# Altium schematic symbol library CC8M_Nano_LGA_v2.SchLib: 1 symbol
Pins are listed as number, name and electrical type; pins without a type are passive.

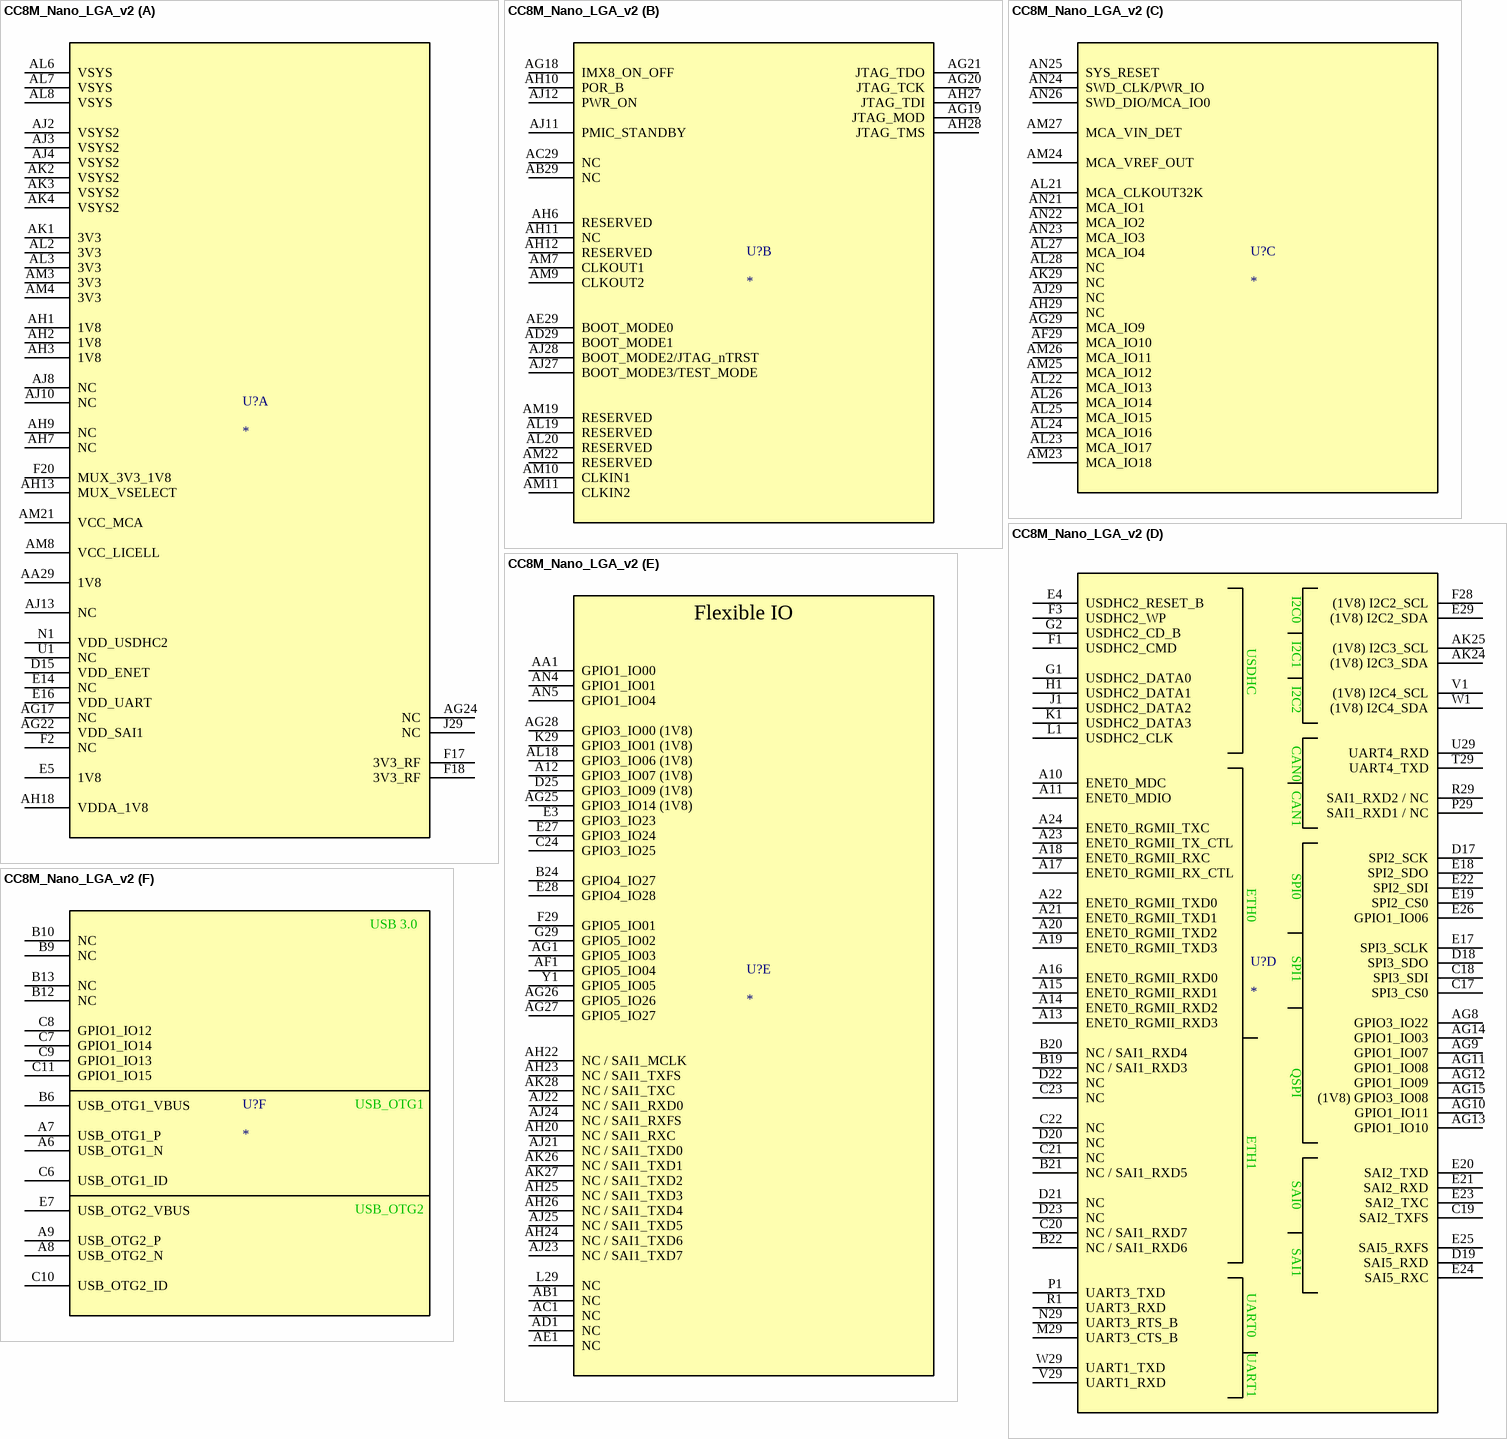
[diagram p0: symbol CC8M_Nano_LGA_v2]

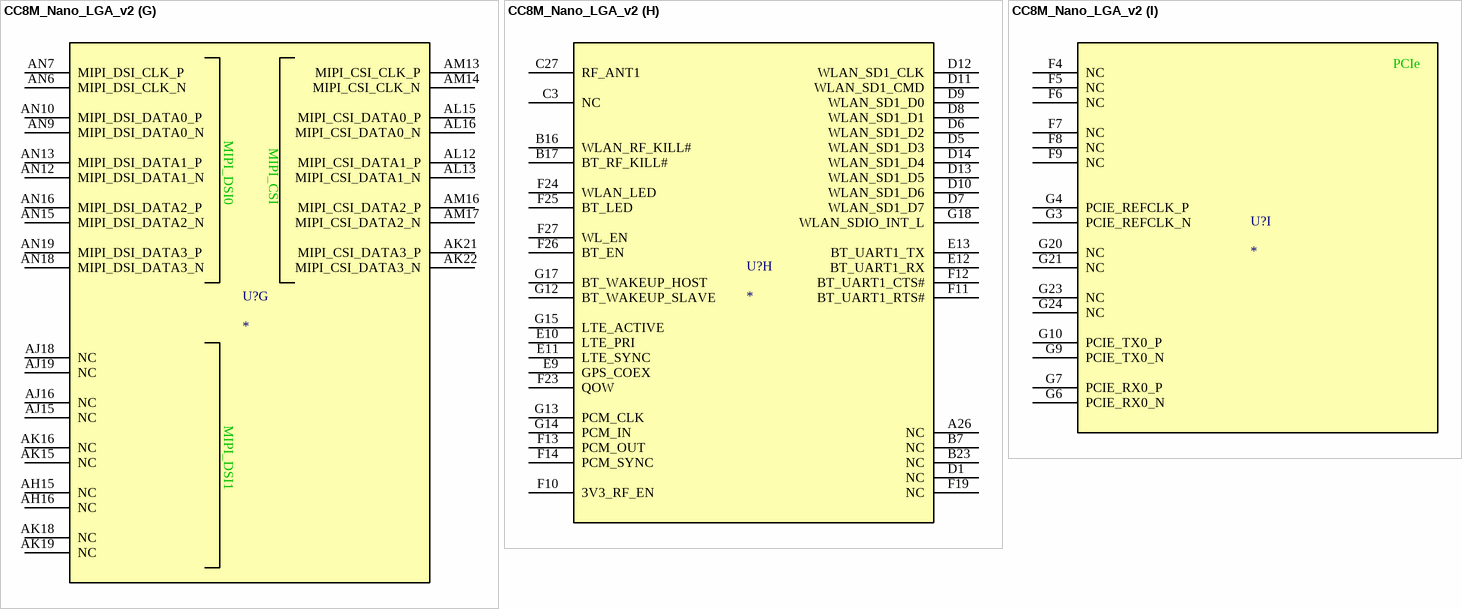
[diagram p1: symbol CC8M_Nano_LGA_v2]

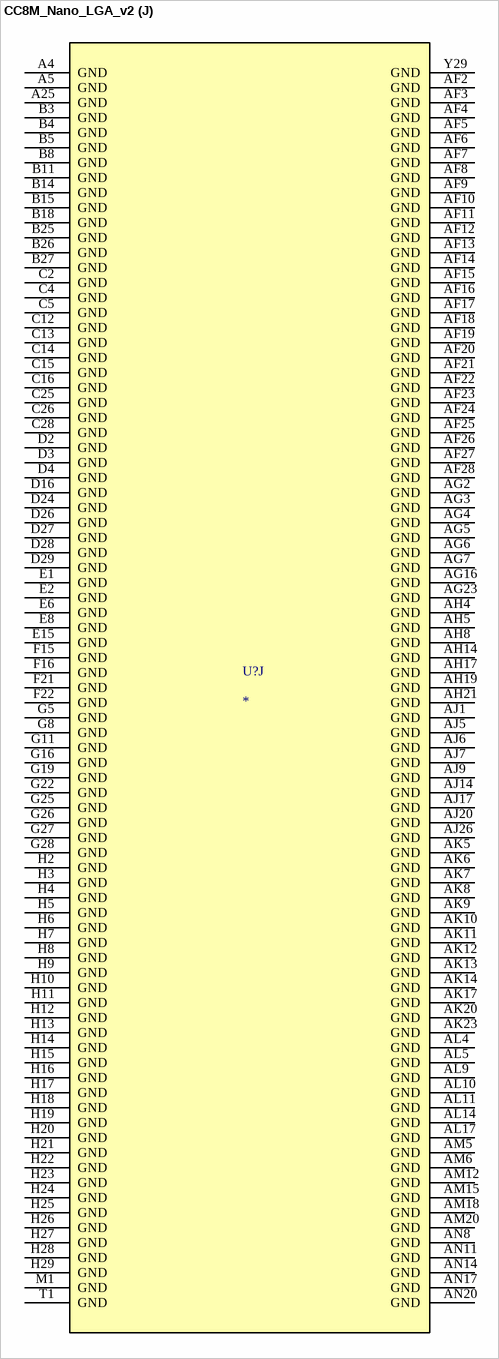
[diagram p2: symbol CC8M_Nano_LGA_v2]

## CC8M_Nano_LGA_v2
designator U?
part A pins: AA29 1V8, AG17 NC, AG22 VDD_SAI1, AG24 NC, AH1 1V8, AH2 1V8, AH3 1V8, AH7 NC, AH9 NC, AH13 MUX_VSELECT, AH18 VDDA_1V8, AJ2 VSYS2, AJ3 VSYS2, AJ4 VSYS2, AJ8 NC, AJ10 NC, AJ13 NC, AK1 3V3, AK2 VSYS2, AK3 VSYS2, AK4 VSYS2, AL2 3V3, AL3 3V3, AL6 VSYS, AL7 VSYS, AL8 VSYS, AM3 3V3, AM4 3V3, AM8 VCC_LICELL, AM21 VCC_MCA, D15 VDD_ENET, E5 1V8, E14 NC, E16 VDD_UART, F2 NC, F17 3V3_RF, F18 3V3_RF, F20 MUX_3V3_1V8, J29 NC, N1 VDD_USDHC2, U1 NC
part B pins: AB29 NC, AC29 NC, AD29 BOOT_MODE1, AE29 BOOT_MODE0, AG18 IMX8_ON_OFF, AG19 JTAG_MOD, AG20 JTAG_TCK, AG21 JTAG_TDO, AH6 RESERVED, AH10 POR_B, AH11 NC, AH12 RESERVED, AH27 JTAG_TDI, AH28 JTAG_TMS, AJ11 PMIC_STANDBY, AJ12 PWR_ON, AJ27 BOOT_MODE3/TEST_MODE, AJ28 BOOT_MODE2/JTAG_nTRST, AL19 RESERVED, AL20 RESERVED, AM7 CLKOUT1, AM9 CLKOUT2, AM10 CLKIN1, AM11 CLKIN2, AM19 RESERVED, AM22 RESERVED
part C pins: AF29 MCA_IO10, AG29 MCA_IO9, AH29 NC, AJ29 NC, AK29 NC, AL21 MCA_CLKOUT32K, AL22 MCA_IO13, AL23 MCA_IO17, AL24 MCA_IO16, AL25 MCA_IO15, AL26 MCA_IO14, AL27 MCA_IO4, AL28 NC, AM23 MCA_IO18, AM24 MCA_VREF_OUT, AM25 MCA_IO12, AM26 MCA_IO11, AM27 MCA_VIN_DET, AN21 MCA_IO1, AN22 MCA_IO2, AN23 MCA_IO3, AN24 SWD_CLK/PWR_IO, AN25 SYS_RESET, AN26 SWD_DIO/MCA_IO0
part D pins: A10 ENET0_MDC, A11 ENET0_MDIO, A13 ENET0_RGMII_RXD3, A14 ENET0_RGMII_RXD2, A15 ENET0_RGMII_RXD1, A16 ENET0_RGMII_RXD0, A17 ENET0_RGMII_RX_CTL, A18 ENET0_RGMII_RXC, A19 ENET0_RGMII_TXD3, A20 ENET0_RGMII_TXD2, A21 ENET0_RGMII_TXD1, A22 ENET0_RGMII_TXD0, A23 ENET0_RGMII_TX_CTL, A24 ENET0_RGMII_TXC, AG8 GPIO3_IO22, AG9 GPIO1_IO07, AG10 GPIO1_IO11, AG11 GPIO1_IO08, AG12 GPIO1_IO09, AG13 GPIO1_IO10, AG14 GPIO1_IO03, AG15 (1V8) GPIO3_IO08, AK24 (1V8) I2C3_SDA, AK25 (1V8) I2C3_SCL, B19 NC / SAI1_RXD3, B20 NC / SAI1_RXD4, B21 NC / SAI1_RXD5, B22 NC / SAI1_RXD6, C17 SPI3_CS0, C18 SPI3_SDI, C19 SAI2_TXFS, C20 NC / SAI1_RXD7, C21 NC, C22 NC, C23 NC, D17 SPI2_SCK, D18 SPI3_SDO, D19 SAI5_RXD, D20 NC, D21 NC, D22 NC, D23 NC, E4 USDHC2_RESET_B, E17 SPI3_SCLK, E18 SPI2_SDO, E19 SPI2_CS0, E20 SAI2_TXD, E21 SAI2_RXD, E22 SPI2_SDI, E23 SAI2_TXC, E24 SAI5_RXC, E25 SAI5_RXFS, E26 GPIO1_IO06, E29 (1V8) I2C2_SDA, F1 USDHC2_CMD, F3 USDHC2_WP, F28 (1V8) I2C2_SCL, G1 USDHC2_DATA0, G2 USDHC2_CD_B, H1 USDHC2_DATA1, J1 USDHC2_DATA2, K1 USDHC2_DATA3, L1 USDHC2_CLK, M29 UART3_CTS_B, N29 UART3_RTS_B, P1 UART3_TXD, P29 SAI1_RXD1 / NC, R1 UART3_RXD, R29 SAI1_RXD2 / NC, T29 UART4_TXD, U29 UART4_RXD, V1 (1V8) I2C4_SCL, V29 UART1_RXD, W1 (1V8) I2C4_SDA, W29 UART1_TXD
part E pins: A12 GPIO3_IO07 (1V8), AA1 GPIO1_IO00, AB1 NC, AC1 NC, AD1 NC, AE1 NC, AF1 GPIO5_IO04, AG1 GPIO5_IO03, AG25 GPIO3_IO14 (1V8), AG26 GPIO5_IO26, AG27 GPIO5_IO27, AG28 GPIO3_IO00 (1V8), AH20 NC / SAI1_RXC, AH22 NC / SAI1_MCLK, AH23 NC / SAI1_TXFS, AH24 NC / SAI1_TXD6, AH25 NC / SAI1_TXD3, AH26 NC / SAI1_TXD4, AJ21 NC / SAI1_TXD0, AJ22 NC / SAI1_RXD0, AJ23 NC / SAI1_TXD7, AJ24 NC / SAI1_RXFS, AJ25 NC / SAI1_TXD5, AK26 NC / SAI1_TXD1, AK27 NC / SAI1_TXD2, AK28 NC / SAI1_TXC, AL18 GPIO3_IO06 (1V8), AN4 GPIO1_IO01, AN5 GPIO1_IO04, B24 GPIO4_IO27, C24 GPIO3_IO25, D25 GPIO3_IO09 (1V8), E3 GPIO3_IO23, E27 GPIO3_IO24, E28 GPIO4_IO28, F29 GPIO5_IO01, G29 GPIO5_IO02, K29 GPIO3_IO01 (1V8), L29 NC, Y1 GPIO5_IO05
part F pins: A6 USB_OTG1_N, A7 USB_OTG1_P, A8 USB_OTG2_N, A9 USB_OTG2_P, B6 USB_OTG1_VBUS, B9 NC, B10 NC, B12 NC, B13 NC, C6 USB_OTG1_ID, C7 GPIO1_IO14, C8 GPIO1_IO12, C9 GPIO1_IO13, C10 USB_OTG2_ID, C11 GPIO1_IO15, E7 USB_OTG2_VBUS
part G pins: AH15 NC, AH16 NC, AJ15 NC, AJ16 NC, AJ18 NC, AJ19 NC, AK15 NC, AK16 NC, AK18 NC, AK19 NC, AK21 MIPI_CSI_DATA3_P, AK22 MIPI_CSI_DATA3_N, AL12 MIPI_CSI_DATA1_P, AL13 MIPI_CSI_DATA1_N, AL15 MIPI_CSI_DATA0_P, AL16 MIPI_CSI_DATA0_N, AM13 MIPI_CSI_CLK_P, AM14 MIPI_CSI_CLK_N, AM16 MIPI_CSI_DATA2_P, AM17 MIPI_CSI_DATA2_N, AN6 MIPI_DSI_CLK_N, AN7 MIPI_DSI_CLK_P, AN9 MIPI_DSI_DATA0_N, AN10 MIPI_DSI_DATA0_P, AN12 MIPI_DSI_DATA1_N, AN13 MIPI_DSI_DATA1_P, AN15 MIPI_DSI_DATA2_N, AN16 MIPI_DSI_DATA2_P, AN18 MIPI_DSI_DATA3_N, AN19 MIPI_DSI_DATA3_P
part H pins: A26 NC, B7 NC, B16 WLAN_RF_KILL#, B17 BT_RF_KILL#, B23 NC, C3 NC, C27 RF_ANT1, D1 NC, D5 WLAN_SD1_D3, D6 WLAN_SD1_D2, D7 WLAN_SD1_D7, D8 WLAN_SD1_D1, D9 WLAN_SD1_D0, D10 WLAN_SD1_D6, D11 WLAN_SD1_CMD, D12 WLAN_SD1_CLK, D13 WLAN_SD1_D5, D14 WLAN_SD1_D4, E9 GPS_COEX, E10 LTE_PRI, E11 LTE_SYNC, E12 BT_UART1_RX, E13 BT_UART1_TX, F10 3V3_RF_EN, F11 BT_UART1_RTS#, F12 BT_UART1_CTS#, F13 PCM_OUT, F14 PCM_SYNC, F19 NC, F23 QOW, F24 WLAN_LED, F25 BT_LED, F26 BT_EN, F27 WL_EN, G12 BT_WAKEUP_SLAVE, G13 PCM_CLK, G14 PCM_IN, G15 LTE_ACTIVE, G17 BT_WAKEUP_HOST, G18 WLAN_SDIO_INT_L
part I pins: F4 NC, F5 NC, F6 NC, F7 NC, F8 NC, F9 NC, G3 PCIE_REFCLK_N, G4 PCIE_REFCLK_P, G6 PCIE_RX0_N, G7 PCIE_RX0_P, G9 PCIE_TX0_N, G10 PCIE_TX0_P, G20 NC, G21 NC, G23 NC, G24 NC
part J pins:  A25 GND, A4 GND, A5 GND, AF2 GND, AF3 GND, AF4 GND, AF5 GND, AF6 GND, AF7 GND, AF8 GND, AF9 GND, AF10 GND, AF11 GND, AF12 GND, AF13 GND, AF14 GND, AF15 GND, AF16 GND, AF17 GND, AF18 GND, AF19 GND, AF20 GND, AF21 GND, AF22 GND, AF23 GND, AF24 GND, AF25 GND, AF26 GND, AF27 GND, AF28 GND, AG2 GND, AG3 GND, AG4 GND, AG5 GND, AG6 GND, AG7 GND, AG16 GND, AG23 GND, AH4 GND, AH5 GND, AH8 GND, AH14 GND, AH17 GND, AH19 GND, AH21 GND, AJ1 GND, AJ5 GND, AJ6 GND, AJ7 GND, AJ9 GND, AJ14 GND, AJ17 GND, AJ20 GND, AJ26 GND, AK5 GND, AK6 GND, AK7 GND, AK8 GND, AK9 GND, AK10 GND, AK11 GND, AK12 GND, AK13 GND, AK14 GND, AK17 GND, AK20 GND, AK23 GND, AL4 GND, AL5 GND, AL9 GND, AL10 GND, AL11 GND, AL14 GND, AL17 GND, AM5 GND, AM6 GND, AM12 GND, AM15 GND, AM18 GND, AM20 GND, AN8 GND, AN11 GND, AN14 GND, AN17 GND, AN20 GND, B3 GND, B4 GND, B5 GND, B8 GND, B11 GND, B14 GND, B15 GND, B18 GND, B25 GND, B26 GND, B27 GND, C2 GND, C4 GND, C5 GND, C12 GND, C13 GND, C14 GND, C15 GND, C16 GND, C25 GND, C26 GND, C28 GND, D2 GND, D3 GND, D4 GND, D16 GND, D24 GND, D26 GND, D27 GND, D28 GND, D29 GND, E1 GND, E2 GND, E6 GND, E8 GND, E15 GND, F15 GND, F16 GND, F21 GND, F22 GND, G5 GND, G8 GND, G11 GND, G16 GND, G19 GND, G22 GND, G25 GND, G26 GND, G27 GND, G28 GND, H2 GND, H3 GND, H4 GND, H5 GND, H6 GND, H7 GND, H8 GND, H9 GND, H10 GND, H11 GND, H12 GND, H13 GND, H14 GND, H15 GND, H16 GND, H17 GND, H18 GND, H19 GND, H20 GND, H21 GND, H22 GND, H23 GND, H24 GND, H25 GND, H26 GND, H27 GND, H28 GND, H29 GND, M1 GND, T1 GND, Y29 GND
